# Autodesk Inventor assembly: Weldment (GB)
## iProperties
Length Units: 11269
Angle Units: 11283
Time Units: 11279
Mass Units: 11290
Length Display Precision: 3
Angle Display Precision: 2
Part Number: Weldment (GB)
Document SubType Name: Weldment
Created: 2002-06
Designer: smithga
Created: 2002-08
Control State: 0
Master: False
Shininess: 64.0
Angle Units: 11279
Time Units: 11290
Mass Units: 11283
Compacted: True
Density: 0.0
Volumn: 0.0
Area: 0.0
PropertySet Name: Model Information
